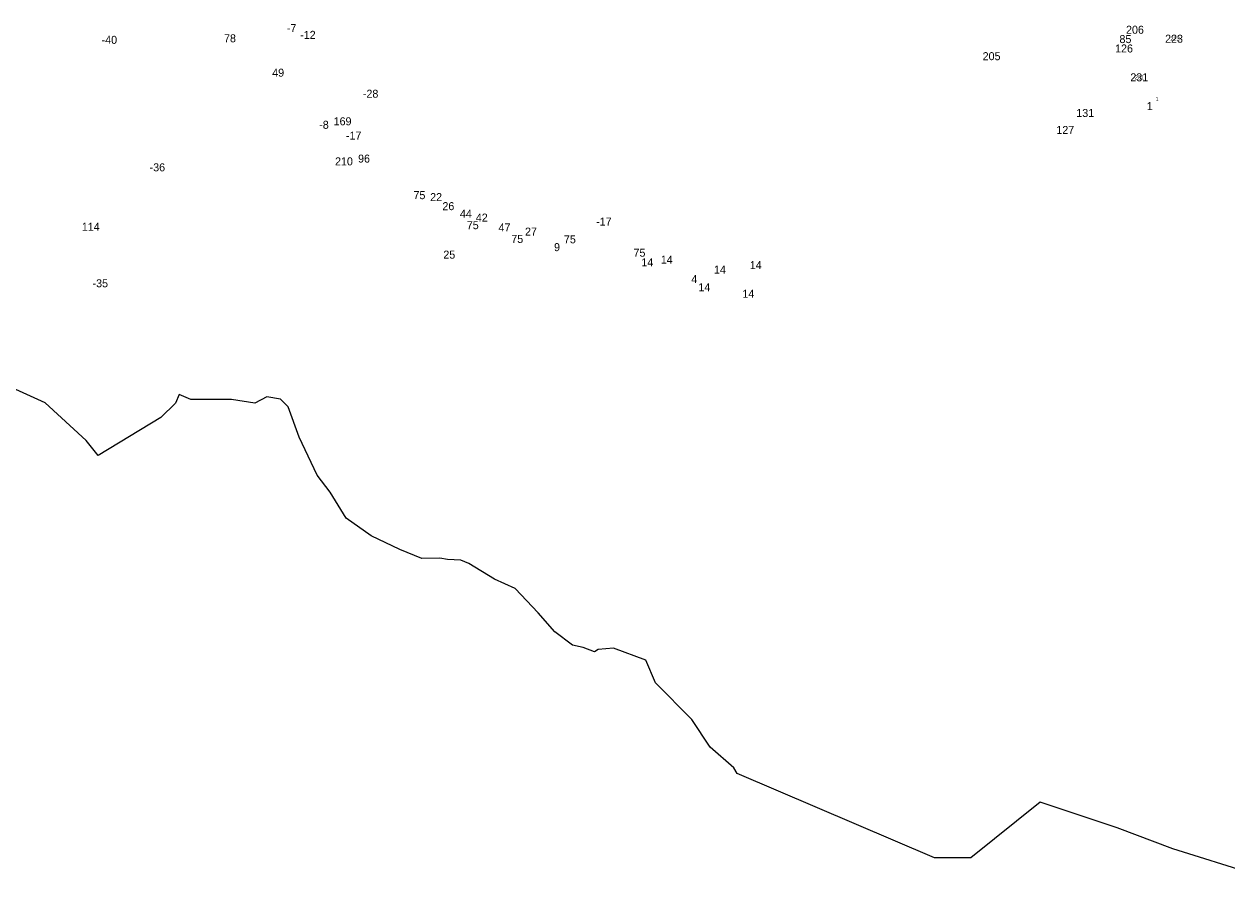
# Model space of a CAD drawing. Extents: x -788870 to -783053, y -967261 to -964403.
# Drawn here: x -785917 to -784414, y -967261 to -966171 of the extents above; entities that cross this region are included whole.
import ezdxf

# ---------------------------------------------------------------- set-up
doc = ezdxf.new("R2010")
doc.units = 0
doc.layers.add('Vrstva 13', color=7, linetype='Continuous')
doc.layers.add('Vrstva 15', color=7, linetype='Continuous')

msp = doc.modelspace()

# ---------------------------------------------------------------- linework, layer by layer
at = {"layer": 'Vrstva 13'}
for p, q in [((-785890.49, -966644.57), (-785963.49, -966611.52)), ((-785723.04, -966634.43), (-785727.4, -966645.15)), ((-785708.27, -966640.51), (-785723.04, -966634.43)), ((-785839.21, -966691.51), (-785890.49, -966644.57)), ((-785727.4, -966645.15), (-785745.94, -966662.82)), ((-785657.58, -966640.51), (-785708.27, -966640.51)), ((-785628.32, -966644.86), (-785657.58, -966640.51)), ((-785613.54, -966637.33), (-785628.32, -966644.86)), ((-785596.45, -966640.22), (-785613.54, -966637.33)), ((-785586.89, -966649.79), (-785596.45, -966640.22)), ((-785572.99, -966687.46), (-785586.89, -966649.79)), ((-785745.94, -966662.82), (-785824.15, -966710.35)), ((-785824.15, -966710.35), (-785839.21, -966691.51)), ((-785550.39, -966734.98), (-785572.99, -966687.46)), ((-785534.45, -966756.43), (-785550.39, -966734.98)), ((-785514.47, -966788.59), (-785534.45, -966756.43)), ((-785482.89, -966810.62), (-785514.47, -966788.59)), ((-785447.26, -966827.71), (-785482.89, -966810.62)), ((-785419.74, -966839.02), (-785447.26, -966827.71)), ((-785397.14, -966838.73), (-785419.74, -966839.02)), ((-785387.87, -966840.47), (-785397.14, -966838.73)), ((-785371.07, -966841.05), (-785387.87, -966840.47)), ((-785361.22, -966845.4), (-785371.07, -966841.05)), ((-785329.07, -966864.81), (-785361.22, -966845.4)), ((-785303, -966876.69), (-785329.07, -966864.81)), ((-785274.61, -966907.12), (-785303, -966876.69)), ((-785253.75, -966930.88), (-785274.61, -966907.12)), ((-785231.73, -966947.4), (-785253.75, -966930.88)), ((-785218.41, -966950.3), (-785231.73, -966947.4)), ((-785203.92, -966955.81), (-785218.41, -966950.3)), ((-785199.58, -966952.91), (-785203.92, -966955.81)), ((-785180.17, -966951.17), (-785199.58, -966952.91)), ((-785139.9, -966966.24), (-785180.17, -966951.17)), ((-785127.74, -966994.35), (-785139.9, -966966.24)), ((-785082.55, -967040.13), (-785127.74, -966994.35)), ((-785059.38, -967074.62), (-785082.55, -967040.13)), ((-785030.12, -967100.41), (-785059.38, -967074.62)), ((-785025.77, -967107.65), (-785030.12, -967100.41)), ((-784779.55, -967212.84), (-785025.77, -967107.65)), ((-784647.16, -967143.58), (-784733.78, -967212.84)), ((-784550.99, -967175.46), (-784647.16, -967143.58)), ((-784481.47, -967201.83), (-784550.99, -967175.46)), ((-784294.33, -967260.65), (-784481.47, -967201.83)), ((-784733.78, -967212.84), (-784779.55, -967212.84))]:
    msp.add_line(p, q, dxfattribs=at)

# ---------------------------------------------------------------- texts
at = {"layer": 'Vrstva 15'}
for s, height, p in [('78', 10, (-785666.855, -966194.24)), ('-7', 10, (-785588.399, -966181.47)), ('-12', 10, (-785571.714, -966189.95)), ('206', 10, (-784540.08, -966183.57)), ('-40', 10, (-785819.766, -966196.17)), ('126', 10, (-784553.734, -966206.98)), ('85', 10, (-784548.276, -966195.24)), ('223', 10, (-784491.276, -966194.78)), ('223', 5, (-784484.603, -966192.28)), ('205', 10, (-784719.196, -966216.61)), ('49', 10, (-785606.666, -966237.24)), ('231', 10, (-784534.741, -966243)), ('231', 5, (-784529.15, -966240.5)), ('-28', 10, (-785493.41, -966263.5)), ('1', 10, (-784514.191, -966278.89)), ('1', 5, (-784503.34, -966267.57)), ('169', 10, (-785529.938, -966297.95)), ('131', 10, (-784602.216, -966287.56)), ('-8', 10, (-785547.95, -966302.31)), ('127', 10, (-784627.13, -966308.74)), ('-17', 10, (-785514.574, -966315.78)), ('96', 10, (-785499.404, -966344.54)), ('-36', 10, (-785759.814, -966355.46)), ('210', 10, (-785528.181, -966348.01)), ('75', 10, (-785430.205, -966390.21)), ('22', 10, (-785409.386, -966392.61)), ('26', 10, (-785394.08, -966403.97)), ('44', 10, (-785372.198, -966413.51)), ('42', 10, (-785352.312, -966418.26)), ('114', 10, (-785844.462, -966429.64)), ('75', 10, (-785363.585, -966427.72)), ('47', 10, (-785323.971, -966430.61)), ('-17', 10, (-785202.064, -966423.27)), ('75', 10, (-785308.005, -966444.93)), ('27', 10, (-785290.866, -966435.75)), ('75', 10, (-785242.275, -966445.37)), (' 25', 10, (-785396.606, -966464.48)), ('9', 10, (-785254.57, -966455.14)), ('75', 10, (-785155.365, -966462.14)), ('14', 10, (-785145.507, -966474.11)), ('14', 10, (-785121.237, -966470.8)), ('14', 10, (-785010.067, -966477.52)), ('14', 10, (-785054.847, -966483.26)), ('-35', 10, (-785831.09, -966500.3)), ('4', 10, (-785083.122, -966495.1)), ('14', 10, (-785074.267, -966505.22)), ('14', 10, (-785019.357, -966513.44))]:
    msp.add_text(s, height=height, dxfattribs=at).set_placement(p)

doc.saveas('drawing.dxf')
